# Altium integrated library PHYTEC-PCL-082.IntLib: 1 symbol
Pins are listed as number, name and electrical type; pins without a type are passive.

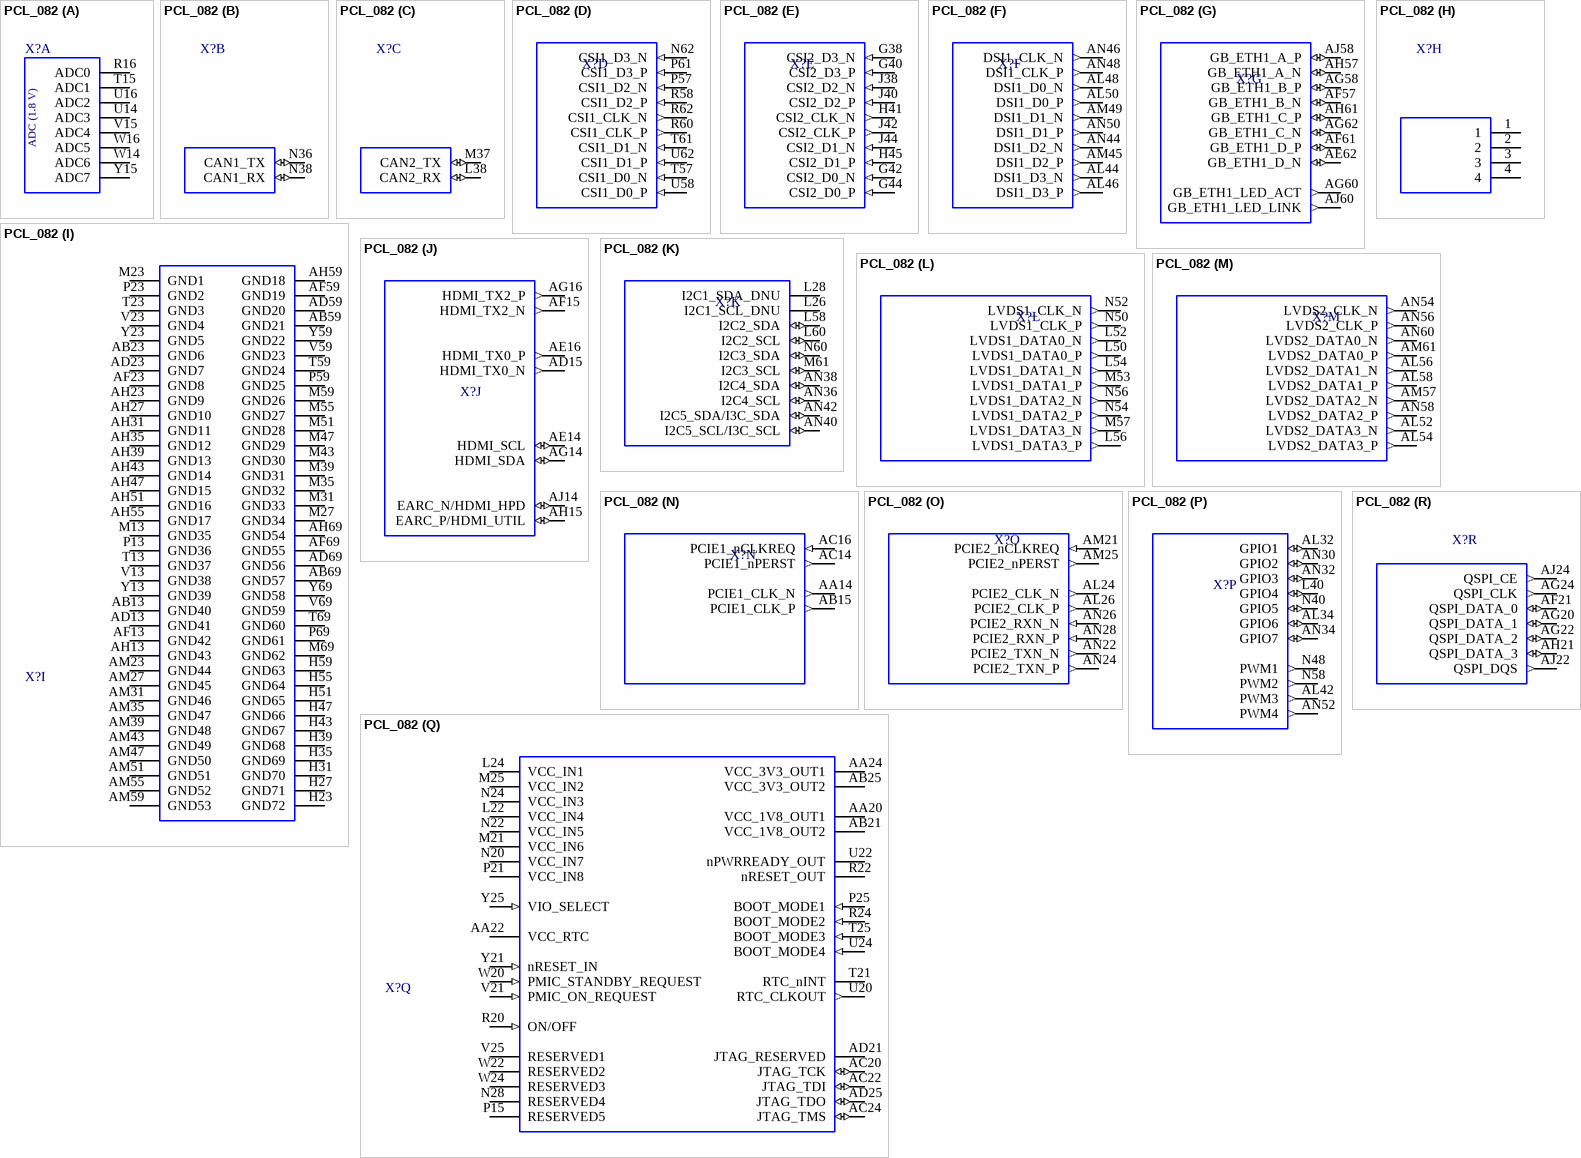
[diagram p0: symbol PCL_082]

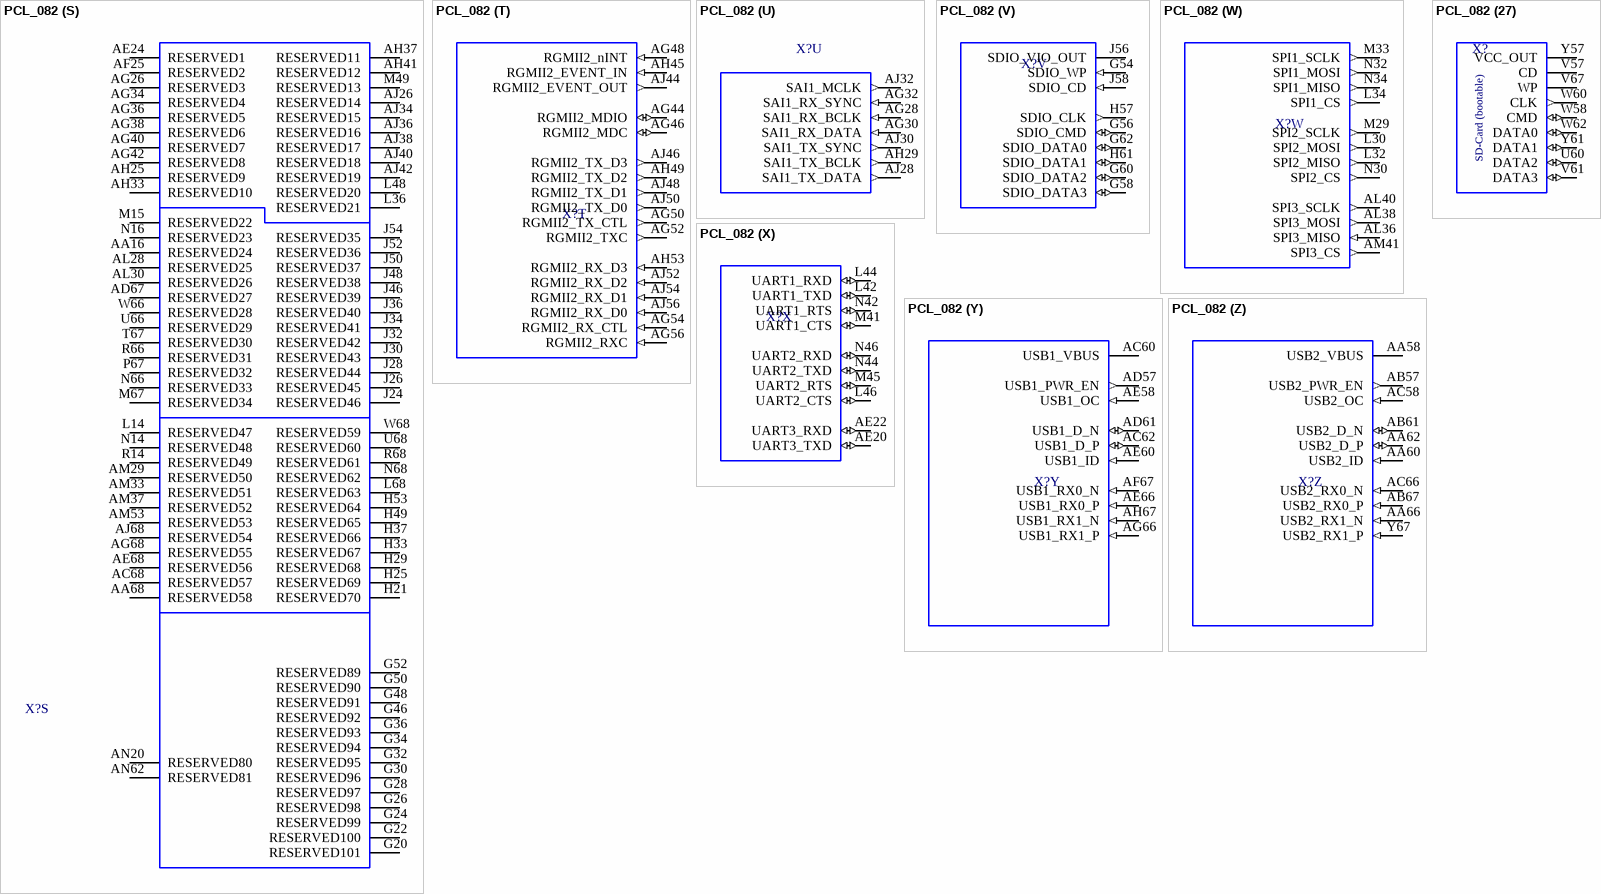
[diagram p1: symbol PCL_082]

## PCL_082
designator X?
footprint PHYTEC-PCL-082 (FPSC for PCL082)
part A pins: R16 ADC0, T15 ADC1, U14 ADC3, U16 ADC2, V15 ADC4, W14 ADC6, W16 ADC5, Y15 ADC7
part B pins: N36 CAN1_TX (io), N38 CAN1_RX (io)
part C pins: L38 CAN2_RX (io), M37 CAN2_TX (io)
part D pins: N62 CSI1_D3_N (in), P57 CSI1_D2_N (in), P61 CSI1_D3_P (in), R58 CSI1_D2_P (in), R60 CSI1_CLK_P (out), R62 CSI1_CLK_N (out), T57 CSI1_D0_N (in), T61 CSI1_D1_N (in), U58 CSI1_D0_P (in), U62 CSI1_D1_P (in)
part E pins: G38 CSI2_D3_N (in), G40 CSI2_D3_P (in), G42 CSI2_D0_N (in), G44 CSI2_D0_P (in), H41 CSI2_CLK_N (out), H45 CSI2_D1_P (in), J38 CSI2_D2_N (in), J40 CSI2_D2_P (in), J42 CSI2_CLK_P (out), J44 CSI2_D1_N (in)
part F pins: AL44 DSI1_D3_N (out), AL46 DSI1_D3_P (out), AL48 DSI1_D0_N (out), AL50 DSI1_D0_P (out), AM45 DSI1_D2_P (out), AM49 DSI1_D1_N (out), AN44 DSI1_D2_N (out), AN46 DSI1_CLK_N (out), AN48 DSI1_CLK_P (out), AN50 DSI1_D1_P (out)
part G pins: AE62 GB_ETH1_D_N (io), AF57 GB_ETH1_B_N (io), AF61 GB_ETH1_D_P (io), AG58 GB_ETH1_B_P (io), AG60 GB_ETH1_LED_ACT (out), AG62 GB_ETH1_C_N (io), AH57 GB_ETH1_A_N (io), AH61 GB_ETH1_C_P (io), AJ58 GB_ETH1_A_P (io), AJ60 GB_ETH1_LED_LINK (out)
part H pins: 1 (power), 2 (power), 3 (power), 4 (power)
part I pins: AB13 GND40 (power), AB23 GND6 (power), AB59 GND21 (power), AB69 GND57 (power), AD13 GND41 (power), AD23 GND7 (power), AD59 GND20 (power), AD69 GND56 (power), AF13 GND42 (power), AF23 GND8 (power), AF59 GND19 (power), AF69 GND55 (power), AH13 GND43 (power), AH23 GND9 (power), AH27 GND10 (power), AH31 GND11 (power), AH35 GND12 (power), AH39 GND13 (power), AH43 GND14 (power), AH47 GND15 (power), AH51 GND16 (power), AH55 GND17 (power), AH59 GND18 (power), AH69 GND54 (power), AM23 GND44 (power), AM27 GND45 (power), AM31 GND46 (power), AM35 GND47 (power), AM39 GND48 (power), AM43 GND49 (power), AM47 GND50 (power), AM51 GND51 (power), AM55 GND52 (power), AM59 GND53 (power), H23 GND72 (power), H27 GND71 (power), H31 GND70 (power), H35 GND69 (power), H39 GND68 (power), H43 GND67 (power), H47 GND66 (power), H51 GND65 (power), H55 GND64 (power), H59 GND63 (power), M13 GND35 (power), M23 GND1 (power), M27 GND34 (power), M31 GND33 (power), M35 GND32 (power), M39 GND31 (power), M43 GND30 (power), M47 GND29 (power), M51 GND28 (power), M55 GND27 (power), M59 GND26 (power), M69 GND62 (power), P13 GND36 (power), P23 GND2 (power), P59 GND25 (power), P69 GND61 (power), T13 GND37 (power), T23 GND3 (power), T59 GND24 (power), T69 GND60 (power), V13 GND38 (power), V23 GND4 (power), V59 GND23 (power), V69 GND59 (power), Y13 GND39 (power), Y23 GND5 (power), Y59 GND22 (power), Y69 GND58 (power)
part J pins: AD15 HDMI_TX0_N (out), AE14 HDMI_SCL (io), AE16 HDMI_TX0_P (out), AF15 HDMI_TX2_N (out), AG14 HDMI_SDA (io), AG16 HDMI_TX2_P (out), AH15 EARC_P/HDMI_UTIL (io), AJ14 EARC_N/HDMI_HPD (io)
part K pins: AN36 I2C4_SCL (io), AN38 I2C4_SDA (io), AN40 I2C5_SCL/I3C_SCL (io), AN42 I2C5_SDA/I3C_SDA (io), L26 I2C1_SCL_DNU (oc), L28 I2C1_SDA_DNU (oc), L58 I2C2_SDA (io), L60 I2C2_SCL (io), M61 I2C3_SCL (io), N60 I2C3_SDA (io)
part L pins: L50 LVDS1_DATA0_P (out), L52 LVDS1_DATA0_N (out), L54 LVDS1_DATA1_N (out), L56 LVDS1_DATA3_P (out), M53 LVDS1_DATA1_P (out), M57 LVDS1_DATA3_N (out), N50 LVDS1_CLK_P (out), N52 LVDS1_CLK_N (out), N54 LVDS1_DATA2_P (out), N56 LVDS1_DATA2_N (out)
part M pins: AL52 LVDS2_DATA3_N (out), AL54 LVDS2_DATA3_P (out), AL56 LVDS2_DATA1_N (out), AL58 LVDS2_DATA1_P (out), AM57 LVDS2_DATA2_N (out), AM61 LVDS2_DATA0_P (out), AN54 LVDS2_CLK_N (out), AN56 LVDS2_CLK_P (out), AN58 LVDS2_DATA2_P (out), AN60 LVDS2_DATA0_N (out)
part N pins: AA14 PCIE1_CLK_N (out), AB15 PCIE1_CLK_P (out), AC14 PCIE1_nPERST (out), AC16 PCIE1_nCLKREQ (in)
part O pins: AL24 PCIE2_CLK_N (out), AL26 PCIE2_CLK_P (out), AM21 PCIE2_nCLKREQ (in), AM25 PCIE2_nPERST (out), AN22 PCIE2_TXN_N (out), AN24 PCIE2_TXN_P (out), AN26 PCIE2_RXN_N (in), AN28 PCIE2_RXN_P (in)
part P pins: AL32 GPIO1 (io), AL34 GPIO6 (io), AL42 PWM3 (out), AN30 GPIO2 (io), AN32 GPIO3 (io), AN34 GPIO7 (io), AN52 PWM4 (out), L40 GPIO4 (io), N40 GPIO5 (io), N48 PWM1 (out), N58 PWM2 (out)
part Q pins: AA20 VCC_1V8_OUT1 (power), AA22 VCC_RTC (power), AA24 VCC_3V3_OUT1 (power), AB21 VCC_1V8_OUT2 (power), AB25 VCC_3V3_OUT2 (power), AC20 JTAG_TCK (io), AC22 JTAG_TDI (io), AC24 JTAG_TMS (io), AD21 JTAG_RESERVED, AD25 JTAG_TDO (io), L22 VCC_IN4 (power), L24 VCC_IN1 (power), M21 VCC_IN6 (power), M25 VCC_IN2 (power), N20 VCC_IN7 (power), N22 VCC_IN5 (power), N24 VCC_IN3 (power), N28 RESERVED4, P15 RESERVED5, P21 VCC_IN8 (power), P25 BOOT_MODE1 (in), R20 ON/OFF (in), R22 nRESET_OUT (oc), R24 BOOT_MODE2 (in), T21 RTC_nINT (oc), T25 BOOT_MODE3 (in), U20 RTC_CLKOUT (out), U22 nPWRREADY_OUT (oc), U24 BOOT_MODE4 (in), V21 PMIC_ON_REQUEST (in), V25 RESERVED1, W20 PMIC_STANDBY_REQUEST (in), W22 RESERVED2, W24 RESERVED3, Y21 nRESET_IN (in), Y25 VIO_SELECT (in)
part R pins: AF21 QSPI_DATA_0 (io), AG20 QSPI_DATA_1 (io), AG22 QSPI_DATA_2 (io), AG24 QSPI_CLK (out), AH21 QSPI_DATA_3 (io), AJ22 QSPI_DQS (out), AJ24 QSPI_CE (out)
part S pins: AA16 RESERVED24, AA68 RESERVED58, AC68 RESERVED57, AD67 RESERVED27, AE24 RESERVED1, AE68 RESERVED56, AF25 RESERVED2, AG26 RESERVED3, AG34 RESERVED4, AG36 RESERVED5, AG38 RESERVED6, AG40 RESERVED7, AG42 RESERVED8, AG68 RESERVED55, AH25 RESERVED9, AH33 RESERVED10, AH37 RESERVED11, AH41 RESERVED12, AJ26 RESERVED14, AJ34 RESERVED15, AJ36 RESERVED16, AJ38 RESERVED17, AJ40 RESERVED18, AJ42 RESERVED19, AJ68 RESERVED54, AL28 RESERVED25, AL30 RESERVED26, AM29 RESERVED50, AM33 RESERVED51, AM37 RESERVED52, AM53 RESERVED53, AN20 RESERVED80, AN62 RESERVED81, G20 RESERVED101, G22 RESERVED100, G24 RESERVED99, G26 RESERVED98, G28 RESERVED97, G30 RESERVED96, G32 RESERVED95, G34 RESERVED94, G36 RESERVED93, G46 RESERVED92, G48 RESERVED91, G50 RESERVED90, G52 RESERVED89, H21 RESERVED70, H25 RESERVED69, H29 RESERVED68, H33 RESERVED67, H37 RESERVED66, H49 RESERVED65, H53 RESERVED64, J24 RESERVED46, J26 RESERVED45, J28 RESERVED44, J30 RESERVED43, J32 RESERVED42, J34 RESERVED41, J36 RESERVED40, J46 RESERVED39, J48 RESERVED38, J50 RESERVED37, J52 RESERVED36, J54 RESERVED35, L14 RESERVED47, L36 RESERVED21, L48 RESERVED20, L68 RESERVED63, M15 RESERVED22, M49 RESERVED13, M67 RESERVED34, N14 RESERVED48, N16 RESERVED23, N66 RESERVED33, N68 RESERVED62, P67 RESERVED32, R14 RESERVED49, R66 RESERVED31, R68 RESERVED61, T67 RESERVED30, U66 RESERVED29, U68 RESERVED60, W66 RESERVED28, W68 RESERVED59
part T pins: AG44 RGMII2_MDIO (io), AG46 RGMII2_MDC (io), AG48 RGMII2_nINT (in), AG50 RGMII2_TX_CTL (out), AG52 RGMII2_TXC (out), AG54 RGMII2_RX_CTL (in), AG56 RGMII2_RXC (in), AH45 RGMII2_EVENT_IN (in), AH49 RGMII2_TX_D2 (out), AH53 RGMII2_RX_D3 (in), AJ44 RGMII2_EVENT_OUT (out), AJ46 RGMII2_TX_D3 (out), AJ48 RGMII2_TX_D1 (out), AJ50 RGMII2_TX_D0 (out), AJ52 RGMII2_RX_D2 (in), AJ54 RGMII2_RX_D1 (in), AJ56 RGMII2_RX_D0 (in)
part U pins: AG28 SAI1_RX_BCLK (in), AG30 SAI1_RX_DATA (in), AG32 SAI1_RX_SYNC (in), AH29 SAI1_TX_BCLK (out), AJ28 SAI1_TX_DATA (out), AJ30 SAI1_TX_SYNC (out), AJ32 SAI1_MCLK (out)
part V pins: G54 SDIO_WP (in), G56 SDIO_CMD (io), G58 SDIO_DATA3 (io), G60 SDIO_DATA2 (io), G62 SDIO_DATA0 (io), H57 SDIO_CLK (out), H61 SDIO_DATA1 (io), J56 SDIO_VIO_OUT (power), J58 SDIO_CD (in)
part W pins: AL36 SPI3_MISO (in), AL38 SPI3_MOSI (out), AL40 SPI3_SCLK (out), AM41 SPI3_CS (out), L30 SPI2_MOSI (out), L32 SPI2_MISO (out), L34 SPI1_CS (out), M29 SPI2_SCLK (out), M33 SPI1_SCLK (out), N30 SPI2_CS (out), N32 SPI1_MOSI (out), N34 SPI1_MISO (out)
part X pins: AE20 UART3_TXD (io), AE22 UART3_RXD (io), L42 UART1_TXD (io), L44 UART1_RXD (io), L46 UART2_CTS (io), M41 UART1_CTS (io), M45 UART2_RTS (io), N42 UART1_RTS (io), N44 UART2_TXD (io), N46 UART2_RXD (io)
part Y pins: AC60 USB1_VBUS (power), AC62 USB1_D_P (io), AD57 USB1_PWR_EN (out), AD61 USB1_D_N (io), AE58 USB1_OC (in), AE60 USB1_ID (in), AE66 USB1_RX0_P (in), AF67 USB1_RX0_N (in), AG66 USB1_RX1_P (in), AH67 USB1_RX1_N (in)
part Z pins: AA58 USB2_VBUS (power), AA60 USB2_ID (in), AA62 USB2_D_P (io), AA66 USB2_RX1_N (in), AB57 USB2_PWR_EN (out), AB61 USB2_D_N (io), AB67 USB2_RX0_P (in), AC58 USB2_OC (in), AC66 USB2_RX0_N (in), Y67 USB2_RX1_P (in)
part 27 pins: U60 DATA2 (io), V57 CD (oc), V61 DATA3 (io), V67 WP (oc), W58 CMD (io), W60 CLK (out), W62 DATA0 (io), Y57 VCC_OUT (power), Y61 DATA1 (io)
